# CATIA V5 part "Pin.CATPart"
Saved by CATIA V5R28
Part number: Pin
Material "Bordeaux Red": density 7860 kg/m3, Young's modulus 2e+11 Pa, Poisson ratio 0.266
Bounding box of the stored display mesh (mm): x -12.5 to 12.5, y -12.31 to 12.31, z -9 to 96
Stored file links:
  C:\Users\Parisa\Desktop\tarah sanat\Universal Coupling\Pin.CATPart
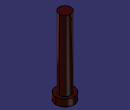
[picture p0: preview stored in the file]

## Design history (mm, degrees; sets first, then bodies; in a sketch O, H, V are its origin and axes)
Body1 "Pin" (main body), material "Bordeaux Red"
  Sketch1 on xy-plane, origin (0, 0, 0), H (1, 0, 0), V (0, 1, 0)
    circle A1 centre (0, 0) radius 12.5
    radius A1 = 12.5
  Pad1: profile Sketch1, direction (0, 0, -1), length 9
  Sketch2 on start face of Pad1, origin (0, 0, 0), H (1, 0, 0), V (0, 1, 0)
    circle A1 centre (0, 0) radius 8
    radius A1 = 8
  Pad2: profile Sketch2, direction (0, 0, 1), length 96
  Sketch3 on yz-plane, origin (0, 0, 0), H (0, 1, 0), V (0, 0, 1)
    line L1 (0, 89) -> (15, 89)
    point P1 (0, 89)
    point P2 (15, 89)
    reference projected line E1 through (0, 0) direction (0, 1) from axis of face of Pad2 from Sketch2.A1
    point P5 (-15, 89)
    point P6 (0, 89)
    line L2 (0, 89) -> (-15, 89)
    point P7 (-15, 89)
    line L3 (-15, 89) -> (-15, 91)
    line L4 (-15, 91) -> (15, 89.9996)
    line L5 (15, 89.9996) -> (15, 89)
    length L1 = 15
    distance L1 O = 89
    distance P7 P5 = 0
    length L3 = 2
    angle L3 L4 = 88.09
    coincidence: P1 V, P1 P6
    horizontal: L1 H
    symmetry: P2 P5 E1, P1 P6 E1, L1 L2 E1
    vertical: L3 V, L5 V
  Groove1: profile Sketch3, axis Sketch3.L2, angle 360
